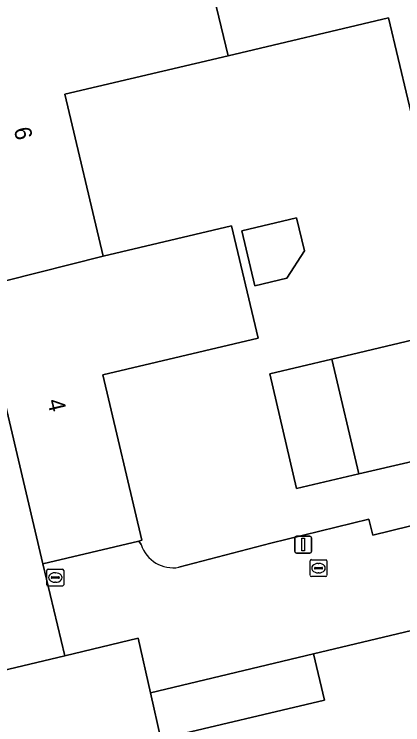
# Model space of a CAD drawing. Extents: x 157648 to 158502, y 379212 to 380938.
# Drawn here: x 158245.9 to 158268.9, y 380707 to 380749.02 of the extents above; entities that cross this region are included whole.
import ezdxf

# ---------------------------------------------------------------- set-up
doc = ezdxf.new("R2010")
doc.units = 0
for name, color, linetype in [('IMGEO_Erf', 7, 'Continuous'), ('IMGEO_Hek', 7, 'Continuous'), ('IMGEO_Kolk', 7, 'Continuous'), ('IMGEO_Lichtmast', 7, 'Continuous'), ('IMGEO_Pand', 7, 'Continuous'), ('IMGEO_Pand_nummerreeks', 7, 'Continuous'), ('IMGEO_Rijbaan_lokaal_open', 7, 'Continuous')]:
    doc.layers.add(name, color=color, linetype=linetype)

msp = doc.modelspace()

# ---------------------------------------------------------------- linework, layer by layer
at = {"layer": 'IMGEO_Erf'}
for points in [[(158272.26, 380739.64), (158270.333, 380739.185), (158268.058, 380748.813), (158258.559, 380746.568), (158248.902, 380744.286), (158251.165, 380734.711), (158258.765, 380736.507), (158260.334, 380729.868), (158251.15, 380727.697), (158253.462, 380717.912), (158253.285, 380717.87), (158253.417, 380717.657)], [(158255.652, 380716.314), (158261.084, 380717.74), (158266.879, 380719.16), (158267.114, 380718.206), (158276.849, 380720.602), (158276.608, 380721.554), (158276.017, 380724.096), (158266.293, 380721.834), (158262.617, 380720.979), (158261.039, 380727.764), (158264.689, 380728.626), (158274.324, 380730.903), (158272.26, 380739.64)]]:
    msp.add_lwpolyline(points, dxfattribs=at)
for points in [[(158262.026, 380733.403), (158260.137, 380732.957), (158259.369, 380736.207), (158262.616, 380736.974), (158263.076, 380735.029)], [(158253.97, 380708.886), (158254.589, 380706.162), (158264.273, 380708.45), (158263.621, 380711.19)]]:
    msp.add_lwpolyline(points, close=True, dxfattribs=at)
msp.add_arc((158255.31, 380718.276), 1.992, 198.108, 279.8891, dxfattribs=at)
at = {"layer": 'IMGEO_Hek'}
for points in [[(158253.417, 380717.657), (158253.285, 380717.87)], [(158261.084, 380717.74), (158255.652, 380716.314)]]:
    msp.add_lwpolyline(points, dxfattribs=at)
msp.add_arc((158255.31, 380718.276), 1.992, 198.108, 279.8891, dxfattribs=at)
at = {"layer": 'IMGEO_Kolk'}
for p, q in [((158263.41, 380715.84), (158263.41, 380716.692)), ((158263.485, 380716.766), (158264.337, 380716.766)), ((158263.898, 380716.546), (158263.923, 380716.546)), ((158264.411, 380716.692), (158264.411, 380715.84)), ((158247.832, 380715.282), (158247.832, 380716.134)), ((158247.907, 380716.208), (158248.759, 380716.208)), ((158248.833, 380716.134), (158248.833, 380715.282)), ((158263.669, 380716.26), (158263.669, 380716.272)), ((158264.107, 380716.223), (158263.709, 380716.223)), ((158263.712, 380716.309), (158264.11, 380716.309)), ((158264.153, 380716.272), (158264.153, 380716.26)), ((158248.091, 380715.702), (158248.091, 380715.714)), ((158248.529, 380715.665), (158248.131, 380715.665)), ((158248.134, 380715.751), (158248.532, 380715.751)), ((158248.32, 380715.988), (158248.345, 380715.988)), ((158248.575, 380715.714), (158248.575, 380715.702)), ((158264.337, 380715.766), (158263.485, 380715.766)), ((158263.921, 380715.986), (158263.896, 380715.986)), ((158248.759, 380715.208), (158247.907, 380715.208)), ((158248.343, 380715.428), (158248.318, 380715.428))]:
    msp.add_line(p, q, dxfattribs=at)
for points in [[(158263.41, 380715.84), (158263.41, 380716.692)], [(158263.485, 380716.766), (158264.337, 380716.766)], [(158264.411, 380716.692), (158264.411, 380715.84)], [(158247.832, 380715.282), (158247.832, 380716.134)], [(158247.907, 380716.208), (158248.759, 380716.208)], [(158248.833, 380716.134), (158248.833, 380715.282)], [(158264.337, 380715.766), (158263.485, 380715.766)], [(158248.759, 380715.208), (158247.907, 380715.208)]]:
    msp.add_lwpolyline(points, dxfattribs=at)
for centre, radius, start, end in [((158263.487, 380716.69), 0.0765, 91.552, 178.448), ((158263.487, 380716.69), 0.0765, 91.552, 178.448), ((158264.335, 380716.69), 0.0765, 1.552, 88.448), ((158264.335, 380716.69), 0.0765, 1.552, 88.448), ((158247.909, 380716.132), 0.0765, 91.552, 178.448), ((158247.909, 380716.132), 0.0765, 91.552, 178.448), ((158248.757, 380716.132), 0.0765, 1.552, 88.448), ((158248.757, 380716.132), 0.0765, 1.552, 88.448), ((158263.709, 380716.269), 0.0403, 85.8775, 175.7526), ((158263.706, 380716.259), 0.0366, 178.938, 274.7102), ((158264.11, 380716.266), 0.043, 264.8664, 352.4533), ((158264.114, 380716.271), 0.0386, 1.7309, 96.639), ((158248.131, 380715.711), 0.0403, 85.8775, 175.7526), ((158248.128, 380715.701), 0.0366, 178.938, 274.7102), ((158248.532, 380715.708), 0.043, 264.8664, 352.4533), ((158248.536, 380715.713), 0.0386, 1.7309, 96.639), ((158263.487, 380715.842), 0.0765, 181.552, 268.448), ((158263.487, 380715.842), 0.0765, 181.552, 268.448), ((158264.335, 380715.842), 0.0765, 271.552, 358.448), ((158264.335, 380715.842), 0.0765, 271.552, 358.448), ((158247.909, 380715.284), 0.0765, 181.552, 268.448), ((158247.909, 380715.284), 0.0765, 181.552, 268.448), ((158248.757, 380715.284), 0.0765, 271.552, 358.448), ((158248.757, 380715.284), 0.0765, 271.552, 358.448)]:
    msp.add_arc(centre, radius, start, end, dxfattribs=at)
for centre, major_axis, ratio, start_param, end_param in [((158263.897, 380716.266), (-0.387, 0.002), 0.722429, 4.712389, 7.853982), ((158263.922, 380716.266), (-0.39, 0.002), 0.717154, 1.570796, 4.712389), ((158248.319, 380715.708), (-0.387, 0.002), 0.722429, 4.712389, 7.853982), ((158248.344, 380715.708), (-0.39, 0.002), 0.717154, 1.570796, 4.712389)]:
    msp.add_ellipse(centre, major_axis=major_axis, ratio=ratio, start_param=start_param, end_param=end_param, dxfattribs=at)
at = {"layer": 'IMGEO_Lichtmast'}
for p, q in [((158262.607, 380718.154), (158263.397, 380718.154)), ((158263.397, 380718.154), (158262.607, 380718.154)), ((158262.507, 380717.254), (158262.507, 380718.054)), ((158262.507, 380718.054), (158262.507, 380717.254)), ((158263.497, 380718.054), (158263.497, 380717.254)), ((158263.497, 380717.254), (158263.497, 380718.054)), ((158263.397, 380717.154), (158262.607, 380717.154)), ((158262.607, 380717.154), (158263.397, 380717.154))]:
    msp.add_line(p, q, dxfattribs=at)
msp.add_lwpolyline([(158262.927, 380718.029), (158263.077, 380718.029), (158263.077, 380717.279), (158262.927, 380717.279), (158262.927, 380718.029)], dxfattribs=at)
for centre, start, end in [((158262.607, 380718.054), 90, 180), ((158262.607, 380718.054), 90, 180), ((158263.397, 380718.054), 0, 90), ((158263.397, 380718.054), 360, 90), ((158262.607, 380717.254), 180, 270), ((158262.607, 380717.254), 180, 270), ((158263.397, 380717.254), 270, 0), ((158263.397, 380717.254), 270, 0)]:
    msp.add_arc(centre, 0.1, start, end, dxfattribs=at)
at = {"layer": 'IMGEO_Pand'}
for points in [[(158273.769, 380751.827), (158273.435, 380753.237), (158275.19, 380753.654), (158274.307, 380757.374), (158272.309, 380756.906), (158264.306, 380755.031), (158256.966, 380753.286), (158257.745, 380750), (158258.559, 380746.568), (158268.058, 380748.813), (158270.333, 380739.185), (158272.26, 380739.64), (158276.422, 380740.61)], [(158251.165, 380734.711), (158248.902, 380744.286), (158258.559, 380746.568), (158257.745, 380750), (158256.966, 380753.286), (158249.719, 380751.564), (158239.831, 380749.23), (158240.714, 380745.496), (158242.413, 380745.898), (158245.399, 380733.264)], [(158264.689, 380728.626), (158266.293, 380721.834), (158276.017, 380724.096), (158276.608, 380721.554), (158282.457, 380722.915), (158278.162, 380741.009), (158276.422, 380740.61), (158272.26, 380739.64), (158274.324, 380730.903)], [(158262.026, 380733.403), (158263.076, 380735.029), (158262.616, 380736.974), (158259.369, 380736.207), (158260.137, 380732.957)], [(158258.765, 380736.507), (158251.165, 380734.711), (158245.399, 380733.264), (158243.735, 380732.87), (158244.166, 380731.05), (158247.603, 380716.527), (158253.285, 380717.87), (158253.462, 380717.912), (158251.15, 380727.697), (158260.334, 380729.868)], [(158264.689, 380728.626), (158261.039, 380727.764), (158262.617, 380720.979), (158266.293, 380721.834)], [(158254.589, 380706.162), (158256.064, 380699.674), (158265.77, 380701.967), (158267.872, 380693.071), (158273.711, 380694.451), (158271.771, 380702.659), (158270.121, 380709.895), (158269.481, 380712.584), (158269.421, 380712.57), (158263.621, 380711.19), (158264.273, 380708.45)], [(158245.021, 380703.851), (158249.683, 380704.952), (158254.589, 380706.162), (158253.97, 380708.886), (158253.235, 380712.117), (158248.892, 380711.083), (158235.125, 380707.805), (158236.518, 380701.972), (158239.156, 380702.602), (158241.391, 380693.142), (158247.232, 380694.492)]]:
    msp.add_lwpolyline(points, close=True, dxfattribs=at)
at = {"layer": 'IMGEO_Rijbaan_lokaal_open'}
for points in [[(158247.603, 380716.527), (158244.166, 380731.05), (158237.411, 380729.488), (158234.236, 380728.754), (158233.782, 380730.492), (158231.155, 380729.871)], [(158230.481, 380727.87), (158223.363, 380726.13), (158219.966, 380725.316), (158221.618, 380718.692), (158222.507, 380715.126), (158224.836, 380705.355), (158235.125, 380707.805), (158248.892, 380711.083), (158247.603, 380716.527)], [(158285.778, 380724.361), (158285.346, 380724.251), (158285.482, 380723.632), (158285.346, 380723.589), (158282.457, 380722.915), (158276.608, 380721.554), (158276.849, 380720.602), (158267.114, 380718.206), (158266.879, 380719.16), (158261.084, 380717.74), (158255.652, 380716.314)], [(158253.417, 380717.657), (158253.285, 380717.87), (158247.603, 380716.527), (158248.892, 380711.083), (158253.235, 380712.117), (158253.97, 380708.886), (158263.621, 380711.19), (158269.421, 380712.57)]]:
    msp.add_lwpolyline(points, dxfattribs=at)
msp.add_arc((158255.31, 380718.276), 1.992, 198.108, 279.8891, dxfattribs=at)

# ---------------------------------------------------------------- texts
at = {"layer": 'IMGEO_Pand_nummerreeks'}
for s, rotation, p in [('6', 283.2976, (158245.87, 380742.229)), ('4', 283.2924, (158247.853, 380726.16))]:
    msp.add_text(s, height=1, rotation=rotation, dxfattribs=at).set_placement(p)

doc.saveas('drawing.dxf')
